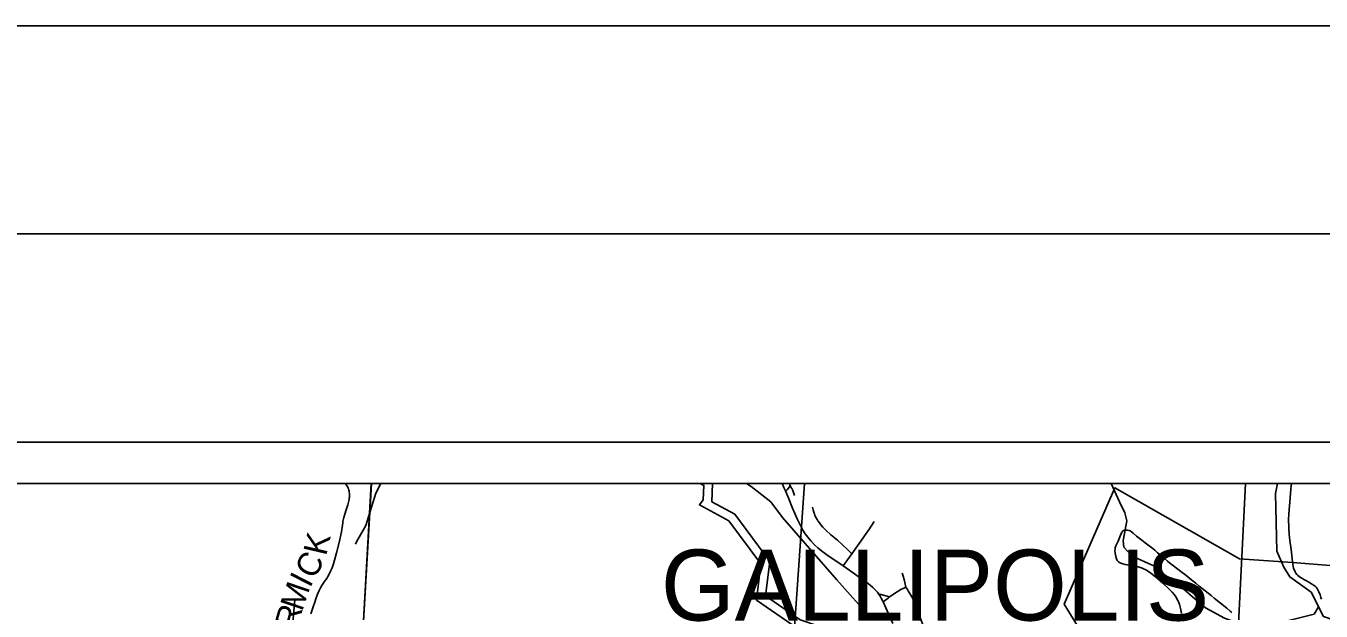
# Model space of a CAD drawing. Extents: x 0 to 34, y 0 to 22.
# Drawn here: x 26.889 to 30.002, y 20.594 to 22 of the extents above; entities that cross this region are included whole.
import ezdxf

# ---------------------------------------------------------------- set-up
doc = ezdxf.new("R2010")
doc.units = 0
for name, color, linetype in [('Default', 7, 'Continuous'), ('GM_X_City_Street', 7, 'Continuous'), ('GM_X_County_Road', 7, 'Continuous'), ('GM_X_County_Road_Text', 7, 'Continuous'), ('GM_X_Minor_River', 7, 'Continuous'), ('GM_X_Rail_Line', 7, 'Continuous'), ('GM_X_State_Route', 7, 'Continuous'), ('GM_X_Township_Road', 7, 'Continuous'), ('GM_X_Township_Text', 7, 'Continuous'), ('SH_Border', 7, 'Continuous'), ('SH_Cut_Line', 7, 'Continuous'), ('SH_Data', 7, 'Continuous'), ('SH_Text', 7, 'Continuous')]:
    doc.layers.add(name, color=color, linetype=linetype)

msp = doc.modelspace()

# ---------------------------------------------------------------- linework, layer by layer
at = {"layer": 'Default'}
for points in [[(27.477, 16.8624), (27.5436, 17.9511), (27.5778, 18.4732), (27.5831, 18.5542), (27.5939, 18.7192), (27.6065, 18.9313), (27.6117, 19.011), (27.6573, 19.7849), (27.6577, 19.7927), (27.658, 19.8018), (27.6584, 19.8127), (27.6591, 19.8289), (27.6592, 19.8432), (27.6592, 19.8474), (27.6594, 19.8586), (27.6594, 19.8591), (27.6594, 19.8627), (27.6594, 19.867), (27.6595, 19.8705), (27.6597, 19.8748), (27.6605, 19.8792), (27.7198, 20.9), (23.5167, 20.9)], [(30.3167, 20.9), (27.7198, 20.9), (27.6605, 19.8792), (27.6597, 19.8748), (27.6595, 19.8705), (27.6594, 19.867), (27.6594, 19.8627), (27.6594, 19.8591), (27.6594, 19.8586), (27.6592, 19.8474), (27.6592, 19.8432), (27.6591, 19.8289), (27.6584, 19.8127), (27.658, 19.8018), (27.6577, 19.7927), (27.6573, 19.7849), (27.6117, 19.011), (27.6065, 18.9313), (27.5939, 18.7192), (27.5831, 18.5542), (27.5778, 18.4732), (27.5436, 17.9511), (27.477, 16.8624)], [(30.1539, 20.6926), (29.9331, 20.7102), (29.8055, 20.7195), (29.5057, 20.8898), (29.3843, 20.61), (29.4399, 20.5188)], [(30.3167, 20.9), (29.8196, 20.9), (29.7719, 19.9386), (29.7988, 19.9402), (29.8261, 19.9433), (29.8337, 19.9437), (29.8473, 19.9438), (29.8591, 19.9453), (29.8716, 19.9469), (29.8844, 19.9492), (29.9, 19.9534), (29.945, 19.9646), (29.9575, 19.968), (29.9791, 19.9738), (29.9957, 19.9772), (30.0188, 19.9811)]]:
    msp.add_lwpolyline(points, dxfattribs=at)
for points in [[(27.7187, 20.9), (26.6756, 20.9), (26.6253, 20.056), (27.6689, 20.0112)], [(28.7599, 20.9), (27.7187, 20.9), (27.6689, 20.0112), (28.6954, 19.9659)], [(29.8196, 20.9), (28.7599, 20.9), (28.6954, 19.9659), (29.6811, 19.9182), (29.6917, 19.9201), (29.703, 19.9232), (29.7227, 19.9266), (29.7379, 19.9286), (29.7546, 19.9305), (29.7719, 19.9386)]]:
    msp.add_lwpolyline(points, close=True, dxfattribs=at)
at = {"layer": 'GM_X_City_Street'}
msp.add_lwpolyline([(29.6664, 20.5881), (29.6642, 20.5967), (29.6628, 20.6031), (29.6612, 20.6093), (29.6604, 20.6121), (29.6597, 20.6143), (29.6575, 20.6192), (29.6528, 20.6276), (29.649, 20.633), (29.6438, 20.6393), (29.6365, 20.6465), (29.6209, 20.6608), (29.6083, 20.6718), (29.5958, 20.6822), (29.5888, 20.6872), (29.5801, 20.6925), (29.5732, 20.6963), (29.5699, 20.6977), (29.5668, 20.6988), (29.5597, 20.7008), (29.5499, 20.7027), (29.5309, 20.7057), (29.5248, 20.7072), (29.5201, 20.7089), (29.5168, 20.7106), (29.5144, 20.7124), (29.5115, 20.7157), (29.5096, 20.7195), (29.5081, 20.7249), (29.5067, 20.7329), (29.5061, 20.7391), (29.5063, 20.7428), (29.5069, 20.7458), (29.5084, 20.7505), (29.5135, 20.7619), (29.5214, 20.7801), (29.5223, 20.7824), (29.5232, 20.7839), (29.5242, 20.7855), (29.5261, 20.787), (29.5284, 20.788), (29.5314, 20.7885), (29.5358, 20.7883), (29.5401, 20.7875), (29.5424, 20.7867), (29.5451, 20.7851), (29.5498, 20.7811), (29.5583, 20.7738), (29.5704, 20.7641), (29.5788, 20.7577), (29.5884, 20.7509), (29.594, 20.7469), (29.5982, 20.7433), (29.6019, 20.74), (29.6087, 20.7336), (29.6115, 20.7311), (29.625, 20.7201), (29.6327, 20.7139), (29.6413, 20.7068), (29.6472, 20.7023), (29.6641, 20.6891), (29.6763, 20.6797), (29.691, 20.6681), (29.7002, 20.6607), (29.7089, 20.6538), (29.7372, 20.6311), (29.7447, 20.625), (29.7749, 20.6004), (29.7828, 20.5938), (29.7871, 20.5902)], dxfattribs=at)
at = {"layer": 'GM_X_County_Road'}
for points in [[(27.5739, 20.5869), (27.5786, 20.6018), (27.5838, 20.6175), (27.5857, 20.6234), (27.5898, 20.6345), (27.5936, 20.6429), (27.5969, 20.6496), (27.6001, 20.6554), (27.603, 20.66), (27.6059, 20.6642), (27.6091, 20.6683), (27.6119, 20.672), (27.6149, 20.6769), (27.6178, 20.6823), (27.6213, 20.69), (27.6246, 20.698), (27.6278, 20.7071), (27.6306, 20.716), (27.6355, 20.7337), (27.6417, 20.7585), (27.6476, 20.7844), (27.6485, 20.7896), (27.6492, 20.7947), (27.6505, 20.8058), (27.6509, 20.8093), (27.6514, 20.8125), (27.6519, 20.8155), (27.6527, 20.8185), (27.6553, 20.827), (27.6587, 20.8374), (27.6625, 20.8494), (27.6643, 20.8553), (27.6651, 20.8586), (27.6657, 20.8616), (27.666, 20.8648), (27.6662, 20.8676), (27.6665, 20.8707), (27.6665, 20.8733), (27.6664, 20.8765), (27.6661, 20.8794), (27.6657, 20.8821), (27.6651, 20.8846), (27.664, 20.8878), (27.6629, 20.8906), (27.6616, 20.8935), (27.6596, 20.8967), (27.6572, 20.8997), (27.6569, 20.9)], [(29.9333, 20.7097), (29.9329, 20.712), (29.9294, 20.7416), (29.9272, 20.7581), (29.9256, 20.7698), (29.9247, 20.7797), (29.924, 20.7915), (29.9237, 20.8021), (29.9236, 20.8076), (29.9236, 20.8095), (29.9236, 20.8143), (29.9241, 20.8261), (29.925, 20.8379), (29.9265, 20.8558), (29.9272, 20.8662), (29.9281, 20.8761), (29.9291, 20.8864), (29.9297, 20.8944), (29.9303, 20.9)], [(30.0025, 20.6222), (30.0013, 20.6263), (29.9992, 20.6327), (29.9964, 20.6401), (29.9941, 20.645), (29.9923, 20.6481), (29.99, 20.6509), (29.9874, 20.6533), (29.9835, 20.6564), (29.9789, 20.6594), (29.9719, 20.6634), (29.9665, 20.6663), (29.9599, 20.6698), (29.955, 20.6726), (29.9518, 20.6745), (29.9487, 20.6767), (29.9457, 20.6791), (29.9431, 20.682), (29.9408, 20.685), (29.9389, 20.6883), (29.9373, 20.6918), (29.9364, 20.6943), (29.9356, 20.6972), (29.9347, 20.7008), (29.9338, 20.7058), (29.9333, 20.7097)]]:
    msp.add_lwpolyline(points, dxfattribs=at)
at = {"layer": 'GM_X_Minor_River'}
for points in [[(27.7416, 20.9), (27.7298, 20.8773), (27.7188, 20.8411), (27.7055, 20.7993), (27.6835, 20.7605), (27.6812, 20.7544)], [(28.5096, 20.9), (28.5182, 20.8959), (28.5168, 20.8613), (28.5074, 20.8487), (28.5785, 20.8106), (28.6551, 20.7069), (28.6444, 20.6203), (28.7402, 20.554), (28.8233, 20.5259), (28.8365, 20.4497), (28.8587, 20.4321), (28.9172, 20.4053), (28.9031, 20.3756), (28.9139, 20.3635), (28.9627, 20.3518), (28.9615, 20.3279), (28.9597, 20.2899), (29.0017, 20.241), (28.9843, 20.167)], [(29.0045, 20.1623), (29.0244, 20.2465), (28.9809, 20.2972), (28.9823, 20.3269), (28.9843, 20.368), (28.9289, 20.3813), (28.945, 20.4154), (28.8697, 20.45), (28.8557, 20.4611), (28.8418, 20.5417), (28.7497, 20.5728), (28.6666, 20.6303), (28.6768, 20.7126), (28.5925, 20.8268), (28.5374, 20.8563), (28.5392, 20.9)], [(29.9955, 20.6036), (29.9847, 20.5866), (29.921, 20.5702), (29.9051, 20.5584), (29.8888, 20.5443), (29.8717, 20.5439), (29.8494, 20.5527), (29.8058, 20.5629), (29.7694, 20.5769), (29.7239, 20.6012), (29.6925, 20.6281), (29.6724, 20.646), (29.6466, 20.6619), (29.6011, 20.7018), (29.5477, 20.7261), (29.5272, 20.7477), (29.5257, 20.7625), (29.5265, 20.7675), (29.5348, 20.8105), (29.5295, 20.8295), (29.5167, 20.8564), (29.497, 20.9)], [(29.863, 20.1034), (29.8497, 20.186), (29.8875, 20.1954), (29.902, 20.221), (29.9219, 20.3259), (30.0153, 20.3837), (30.0611, 20.3917), (30.0774, 20.4833), (30.066, 20.5375), (30.0562, 20.5643), (30.007, 20.5806), (29.9777, 20.6392), (29.9268, 20.6759), (29.9117, 20.6989), (29.8952, 20.7379), (29.8919, 20.8764), (29.8964, 20.9)], [(27.6449, 19.712), (27.6264, 19.8916), (27.5638, 19.9191), (27.5209, 19.9787), (27.52, 20.0436), (27.5369, 20.1158), (27.5291, 20.2467), (27.5281, 20.4376), (27.4991, 20.5098), (27.5306, 20.5663), (27.5352, 20.6206)]]:
    msp.add_lwpolyline(points, dxfattribs=at)
at = {"layer": 'GM_X_Rail_Line'}
msp.add_lwpolyline([(28.6208, 20.9), (28.632, 20.8933), (28.6793, 20.8561), (28.7074, 20.8186), (28.8375, 20.6688), (28.9217, 20.574)], dxfattribs=at)
at = {"layer": 'GM_X_State_Route'}
msp.add_lwpolyline([(28.9721, 20.564), (28.9559, 20.6017), (28.9501, 20.6144), (28.9495, 20.6156), (28.9486, 20.6174), (28.9447, 20.6248), (28.9419, 20.6295), (28.9402, 20.6321), (28.9379, 20.6352), (28.9351, 20.6391), (28.9302, 20.645), (28.9245, 20.6507), (28.9179, 20.6563), (28.9059, 20.6655), (28.8861, 20.6794), (28.8692, 20.691), (28.8531, 20.7021), (28.8137, 20.7291), (28.8007, 20.7386), (28.792, 20.7457), (28.7849, 20.7523), (28.7754, 20.7624), (28.7677, 20.771), (28.7617, 20.7793), (28.7561, 20.7882), (28.7502, 20.7993), (28.7427, 20.8154), (28.7315, 20.8414), (28.7205, 20.8677), (28.714, 20.8826), (28.7106, 20.8905), (28.706, 20.9)], dxfattribs=at)
at = {"layer": 'GM_X_Township_Road'}
for points in [[(28.714, 20.8826), (28.7158, 20.8835), (28.7165, 20.8839), (28.7173, 20.8844), (28.7183, 20.8851), (28.7191, 20.8859), (28.7257, 20.8949), (28.7242, 20.9)], [(28.7364, 20.8715), (28.7327, 20.8813), (28.7318, 20.8833), (28.7312, 20.8848), (28.7305, 20.8865), (28.7298, 20.888), (28.7291, 20.8894), (28.7282, 20.8911), (28.7257, 20.8949)], [(28.8739, 20.7314), (28.8632, 20.7419), (28.8511, 20.7532), (28.8392, 20.764), (28.8237, 20.7773), (28.8113, 20.7881), (28.8086, 20.7907), (28.8065, 20.7927), (28.8047, 20.7947), (28.8038, 20.7957), (28.7991, 20.8014), (28.7974, 20.8036), (28.7934, 20.8091), (28.7921, 20.8109), (28.7903, 20.8139), (28.789, 20.8159), (28.788, 20.8175), (28.7864, 20.8206), (28.7848, 20.8241), (28.7837, 20.8271), (28.7831, 20.8289), (28.7825, 20.8312), (28.781, 20.837), (28.7795, 20.8434)], [(28.9115, 20.785), (28.9143, 20.7891), (28.9277, 20.8094)], [(28.8531, 20.7021), (28.8739, 20.7314), (28.8781, 20.7373), (28.9008, 20.7694), (28.9115, 20.785)], [(29.0032, 20.6513), (29.001, 20.6628), (29.0005, 20.6654), (28.9995, 20.6697), (28.9989, 20.6721), (28.9981, 20.675), (28.9974, 20.6774), (28.995, 20.6852)], [(28.9379, 20.6352), (28.9646, 20.6278), (28.9826, 20.6399), (28.9915, 20.6453), (28.9985, 20.649), (29.0032, 20.6513), (29.0072, 20.6457), (29.0093, 20.6424), (29.0179, 20.6277), (29.0225, 20.6192), (29.025, 20.6138), (29.0287, 20.6049), (29.0564, 20.5281)], [(28.9495, 20.6156), (28.9526, 20.6182), (28.9609, 20.6248), (28.9646, 20.6278)]]:
    msp.add_lwpolyline(points, dxfattribs=at)
at = {"layer": 'SH_Border'}
msp.add_lwpolyline([(1.5, 21.5), (33.5, 21.5), (33.5, 0.5), (1.5, 0.5)], close=True, dxfattribs=at)
at = {"layer": 'SH_Cut_Line'}
msp.add_lwpolyline([(0, 0), (34, 0), (34, 22), (0, 22)], close=True, dxfattribs=at)
at = {"layer": 'SH_Data'}
for points in [[(23.4167, 21), (30.4167, 21), (30.4167, 14), (23.4167, 14)], [(23.5167, 20.9), (30.3167, 20.9), (30.3167, 14.1), (23.5167, 14.1)]]:
    msp.add_lwpolyline(points, close=True, dxfattribs=at)
at = {"layer": 'SH_Text'}
msp.add_lwpolyline([(30.3167, 20.9), (23.5167, 20.9)], dxfattribs=at)

# ---------------------------------------------------------------- texts
at = {"layer": 'GM_X_County_Road_Text'}
for s, rotation, p in [('K', 76.9123, (27.6104, 20.7248)), ('C', 61.2195, (27.5819, 20.6681)), ('I', 62.8345, (27.5715, 20.6477)), ('M', 71.3577, (27.5526, 20.5913)), ('R', 74.4803, (27.5404, 20.5472))]:
    msp.add_text(s, height=0.0568, rotation=rotation, dxfattribs=at).set_placement(p)
at = {"layer": 'GM_X_Township_Text'}
msp.add_text('GALLIPOLIS', height=0.17045, rotation=0, dxfattribs=at).set_placement((28.415, 20.571))

doc.saveas('drawing.dxf')
